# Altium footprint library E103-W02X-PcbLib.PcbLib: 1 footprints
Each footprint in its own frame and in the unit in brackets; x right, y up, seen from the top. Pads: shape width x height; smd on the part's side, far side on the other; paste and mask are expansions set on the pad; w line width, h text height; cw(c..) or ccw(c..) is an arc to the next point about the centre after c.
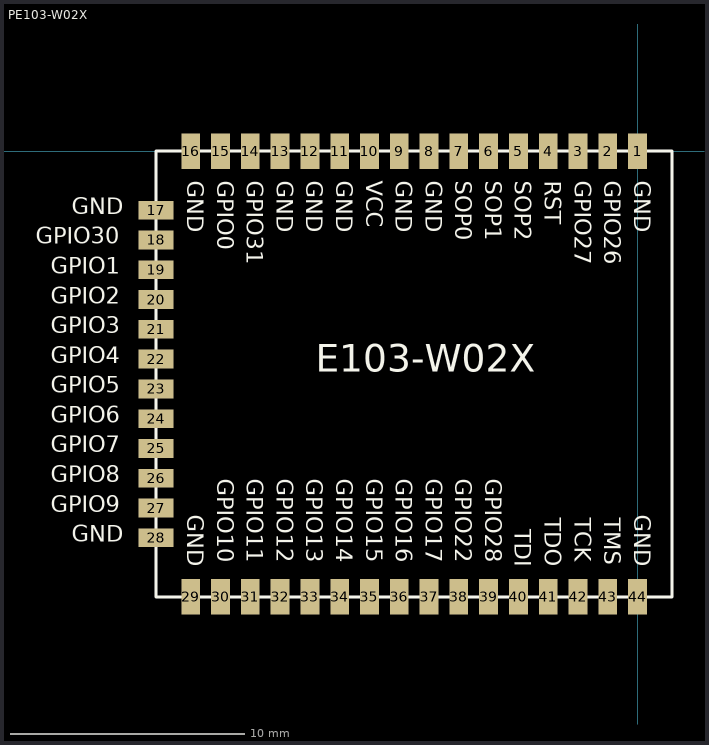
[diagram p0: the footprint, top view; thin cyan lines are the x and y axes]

## PE103-W02X [mm] "27mm*19mm*2.8mm-S"
pads (44):
  rect 0.8x1.5 smd: 1(0,0) 2(-1.27,0) 3(-2.54,0) 4(-3.81,0) 5(-5.08,0) 6(-6.35,0) 7(-7.62,0) 8(-8.89,0) 9(-10.16,0) 10(-11.43,0) 11(-12.7,0) 12(-13.97,0) 13(-15.24,0) 14(-16.51,0) 15(-17.78,0) 16(-19.05,0) 29(-19.05,-19) 30(-17.78,-19) 31(-16.51,-19) 32(-15.24,-19) 33(-13.97,-19) 34(-12.7,-19) 35(-11.43,-19) 36(-10.16,-19) 37(-8.89,-19) 38(-7.62,-19) 39(-6.35,-19) 40(-5.08,-19) 41(-3.81,-19) 42(-2.54,-19) 43(-1.27,-19) 44(0,-19)
  rect 1.5x0.8 smd: 17(-20.525,-2.515) 18(-20.525,-3.785) 19(-20.525,-5.055) 20(-20.525,-6.325) 21(-20.525,-7.595) 22(-20.525,-8.865) 23(-20.525,-10.135) 24(-20.525,-11.405) 25(-20.525,-12.675) 26(-20.525,-13.945) 27(-20.525,-15.215) 28(-20.525,-16.485)
Top Overlay:
  lines w0.127: -20.525,-19 -20.525,0 1.475,0 1.475,-19 -20.525,-19
  text "TDO" at -4.191,-15.621 h1.2
  text "GPIO28" at -6.731,-13.97 h1.2
  text "GPIO22" at -8.001,-13.97 h1.2
  text "GPIO16" at -10.541,-13.97 h1.2
  text "GPIO15" at -11.811,-13.97 h1.2
  text "GPIO13" at -14.351,-13.97 h1.2
  text "GPIO12" at -15.621,-13.97 h1.2
  text "GND" at -0.381,-15.494 h1.2
  text "GND" at -19.431,-15.494 h1.2
  text "GPIO8" at -25.019,-14.351 h1.2
  text "GPIO6" at -25.019,-11.811 h1.2
  text "GPIO4" at -25.019,-9.271 h1.2
  text "GPIO3" at -25.019,-8.001 h1.2
  text "GPIO1" at -25.019,-5.461 h1.2
  text "SOP1" at -6.731,-1.27 h1.2
  text "SOP2" at -5.461,-1.27 h1.2
  text "GPIO27" at -2.921,-1.27 h1.2
  text "GPIO26" at -1.651,-1.27 h1.2
  text "VCC" at -11.811,-1.27 h1.2
  text "E103-W02X" at -13.716,-9.779 h2
  text "GND" at -0.381,-1.27 h1.2
  text "GND" at -9.271,-1.27 h1.2
  text "GND" at -10.541,-1.27 h1.2
  text "GND" at -13.081,-1.27 h1.2
  text "GND" at -14.351,-1.27 h1.2
  text "GND" at -15.621,-1.27 h1.2
  text "RST" at -4.191,-1.27 h1.2
  text "SOP0" at -8.001,-1.27 h1.2
  text "GPIO31" at -16.891,-1.27 h1.2
  text "GPIO0" at -18.161,-1.27 h1.2
  text "GND" at -19.431,-1.27 h1.2
  text "GND" at -24.13,-2.921 h1.2
  text "GPIO30" at -25.654,-4.191 h1.2
  text "GPIO2" at -25.019,-6.731 h1.2
  text "GPIO5" at -25.019,-10.541 h1.2
  text "GPIO7" at -25.019,-13.081 h1.2
  text "GPIO9" at -25.019,-15.621 h1.2
  text "GND" at -24.13,-16.891 h1.2
  text "GPIO10" at -18.161,-13.97 h1.2
  text "GPIO11" at -16.891,-13.97 h1.2
  text "GPIO14" at -13.081,-13.97 h1.2
  text "GPIO17" at -9.271,-13.97 h1.2
  text "TDI" at -5.461,-16.129 h1.2
  text "TCK" at -2.921,-15.621 h1.2
  text "TMS" at -1.651,-15.621 h1.2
